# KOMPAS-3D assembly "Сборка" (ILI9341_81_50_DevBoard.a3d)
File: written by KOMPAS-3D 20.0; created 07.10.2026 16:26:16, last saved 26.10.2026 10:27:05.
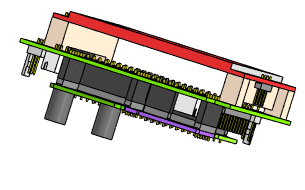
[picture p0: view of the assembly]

Document properties: Полное имя файла: D:\RicWork\Project-EPS32\box_compas\сборки компонентов\ILI9341_81_50_DevBoard.a3d

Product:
- Part/product: Сборка
    Масса: 0.261942
  - Component [assembly]: Сборка  | Масса: 0.132529; source file: макетка+модули.a3d
  - Component [assembly]: Сборка  | Масса: 0.129413; source file: ..\монитор\ILI9341_81_50 asm+.a3d

Referenced files in D:\RicWork\Project-EPS32\box_compas\монитор\: ILI9341_81_50 asm+.a3d
Referenced files in D:\RicWork\Project-EPS32\box_compas\сборки компонентов\: макетка+модули.a3d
